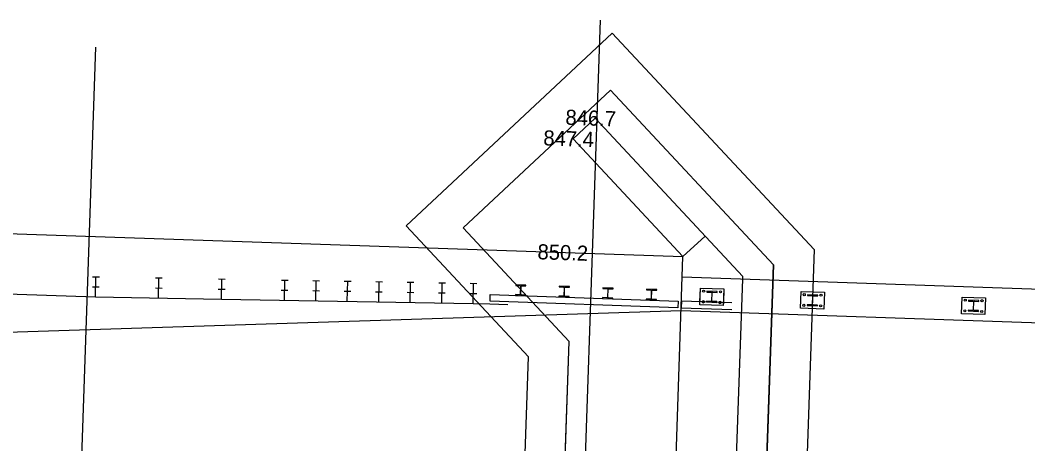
# Model space of a CAD drawing. Extents: x 2191309 to 2193046, y 863659 to 865133.
# Drawn here: x 2191665.3 to 2191715.3, y 865094.6 to 865115.6 of the extents above; entities that cross this region are included whole.
import ezdxf

# ---------------------------------------------------------------- set-up
doc = ezdxf.new("R2010")
doc.units = 0
for name, color, linetype in [('D_Bridge_Abutment', 7, 'Continuous'), ('D_Bridge_Deck', 7, 'Continuous'), ('D_Bridge_Railing', 7, 'Continuous'), ('D_Bridge_Substructure_Hidden', 7, 'Continuous'), ('D_Guardrail_Beam_Lt', 7, 'Continuous'), ('D_Roadway_Edge_Shoulder', 7, 'Continuous'), ('D_Roadway_Edge_TW', 7, 'Continuous'), ('H_V CONTROLS', 7, 'Continuous'), ('JUNK', 7, 'Continuous')]:
    doc.layers.add(name, color=color, linetype=linetype)

msp = doc.modelspace()

# ---------------------------------------------------------------- linework, layer by layer
at = {"layer": 'D_Bridge_Abutment'}
for p, q in [((2191692.707, 865109.691), (2191693.804, 865110.715)), ((2191701.135, 865102.863), (2191693.804, 865110.715)), ((2191698.167, 865103.844), (2191692.707, 865109.691)), ((2191698.167, 865103.844), (2191699.263, 865104.867)), ((2191697, 865069.864), (2191698.167, 865103.844)), ((2191701.131, 865102.741), (2191701.135, 865102.863))]:
    msp.add_line(p, q, dxfattribs=at)
at = {"layer": 'D_Bridge_Deck'}
for p, q in [((2191698.132, 865102.844), (2191735.111, 865101.575)), ((2191698.075, 865101.179), (2191735.053, 865099.909))]:
    msp.add_line(p, q, dxfattribs=at)
at = {"layer": 'D_Bridge_Railing'}
for p, q in [((2191689.861, 865102.451), (2191689.859, 865102.413)), ((2191689.859, 865102.413), (2191690.069, 865102.406)), ((2191690.367, 865102.434), (2191689.861, 865102.451)), ((2191690.098, 865102.375), (2191690.085, 865101.979)), ((2191690.111, 865101.978), (2191690.125, 865102.374)), ((2191690.156, 865102.403), (2191690.366, 865102.396)), ((2191690.366, 865102.396), (2191690.367, 865102.434)), ((2191692.026, 865102.377), (2191692.025, 865102.339)), ((2191692.025, 865102.339), (2191692.235, 865102.332)), ((2191692.532, 865102.359), (2191692.026, 865102.377)), ((2191692.264, 865102.301), (2191692.25, 865101.905)), ((2191692.277, 865101.904), (2191692.29, 865102.3)), ((2191692.321, 865102.329), (2191692.531, 865102.321)), ((2191692.531, 865102.321), (2191692.532, 865102.359)), ((2191694.191, 865102.302), (2191694.19, 865102.264)), ((2191694.19, 865102.264), (2191694.4, 865102.257)), ((2191694.698, 865102.285), (2191694.191, 865102.302)), ((2191694.429, 865102.226), (2191694.415, 865101.83)), ((2191694.442, 865101.829), (2191694.456, 865102.226)), ((2191694.486, 865102.254), (2191694.696, 865102.247)), ((2191694.696, 865102.247), (2191694.698, 865102.285)), ((2191696.357, 865102.228), (2191696.355, 865102.19)), ((2191696.355, 865102.19), (2191696.566, 865102.183)), ((2191696.863, 865102.211), (2191696.357, 865102.228)), ((2191696.652, 865102.18), (2191696.862, 865102.173)), ((2191696.862, 865102.173), (2191696.863, 865102.211)), ((2191689.844, 865101.958), (2191689.842, 865101.92)), ((2191689.842, 865101.92), (2191690.349, 865101.902)), ((2191690.054, 865101.95), (2191689.844, 865101.958)), ((2191690.35, 865101.94), (2191690.14, 865101.947)), ((2191690.349, 865101.902), (2191690.35, 865101.94)), ((2191692.009, 865101.883), (2191692.008, 865101.845)), ((2191692.008, 865101.845), (2191692.514, 865101.828)), ((2191692.219, 865101.876), (2191692.009, 865101.883)), ((2191692.515, 865101.866), (2191692.305, 865101.873)), ((2191692.514, 865101.828), (2191692.515, 865101.866)), ((2191694.174, 865101.809), (2191694.173, 865101.771)), ((2191694.173, 865101.771), (2191694.68, 865101.754)), ((2191694.385, 865101.802), (2191694.174, 865101.809)), ((2191694.681, 865101.791), (2191694.471, 865101.799)), ((2191694.68, 865101.754), (2191694.681, 865101.791)), ((2191696.34, 865101.735), (2191696.339, 865101.697)), ((2191696.339, 865101.697), (2191696.845, 865101.679)), ((2191696.55, 865101.727), (2191696.34, 865101.735)), ((2191696.594, 865102.152), (2191696.581, 865101.756)), ((2191696.607, 865101.755), (2191696.621, 865102.151)), ((2191696.846, 865101.717), (2191696.636, 865101.724)), ((2191696.845, 865101.679), (2191696.846, 865101.717)), ((2191699.353, 865102.125), (2191699.352, 865102.088)), ((2191699.352, 865102.088), (2191699.563, 865102.081)), ((2191699.863, 865102.107), (2191699.353, 865102.125)), ((2191699.355, 865102.125), (2191699.354, 865102.087)), ((2191699.354, 865102.087), (2191699.564, 865102.08)), ((2191699.861, 865102.108), (2191699.355, 865102.125)), ((2191699.593, 865102.049), (2191699.579, 865101.653)), ((2191699.593, 865102.049), (2191699.579, 865101.653)), ((2191699.605, 865101.652), (2191699.619, 865102.048)), ((2191699.606, 865101.652), (2191699.619, 865102.048)), ((2191699.65, 865102.077), (2191699.86, 865102.07)), ((2191699.651, 865102.078), (2191699.862, 865102.071)), ((2191699.86, 865102.07), (2191699.861, 865102.108)), ((2191699.862, 865102.071), (2191699.863, 865102.107)), ((2191704.35, 865101.953), (2191704.349, 865101.917)), ((2191704.349, 865101.917), (2191704.56, 865101.91)), ((2191704.86, 865101.936), (2191704.35, 865101.953)), ((2191704.59, 865101.878), (2191704.576, 865101.481)), ((2191704.602, 865101.48), (2191704.616, 865101.877)), ((2191704.648, 865101.907), (2191704.859, 865101.899)), ((2191704.859, 865101.899), (2191704.86, 865101.936)), ((2191712.345, 865101.679), (2191712.344, 865101.642)), ((2191712.856, 865101.661), (2191712.345, 865101.679)), ((2191699.336, 865101.63), (2191699.335, 865101.594)), ((2191699.335, 865101.594), (2191699.845, 865101.576)), ((2191699.547, 865101.623), (2191699.336, 865101.63)), ((2191699.338, 865101.632), (2191699.337, 865101.594)), ((2191699.337, 865101.594), (2191699.843, 865101.576)), ((2191699.548, 865101.624), (2191699.338, 865101.632)), ((2191699.844, 865101.614), (2191699.634, 865101.621)), ((2191699.846, 865101.613), (2191699.635, 865101.62)), ((2191699.843, 865101.576), (2191699.844, 865101.614)), ((2191699.845, 865101.576), (2191699.846, 865101.613)), ((2191704.333, 865101.459), (2191704.332, 865101.422)), ((2191704.332, 865101.422), (2191704.842, 865101.405)), ((2191704.544, 865101.451), (2191704.333, 865101.459)), ((2191704.843, 865101.441), (2191704.632, 865101.448)), ((2191704.842, 865101.405), (2191704.843, 865101.441)), ((2191712.329, 865101.184), (2191712.327, 865101.148)), ((2191712.54, 865101.177), (2191712.329, 865101.184)), ((2191712.344, 865101.642), (2191712.555, 865101.635)), ((2191712.585, 865101.603), (2191712.572, 865101.207)), ((2191712.598, 865101.206), (2191712.611, 865101.602)), ((2191712.839, 865101.167), (2191712.627, 865101.174)), ((2191712.643, 865101.632), (2191712.854, 865101.625)), ((2191712.837, 865101.13), (2191712.839, 865101.167)), ((2191712.854, 865101.625), (2191712.856, 865101.661)), ((2191712.327, 865101.148), (2191712.837, 865101.13))]:
    msp.add_line(p, q, dxfattribs=at)
for points in [[(2191699.03, 865102.287), (2191700.196, 865102.247), (2191700.168, 865101.414), (2191699.002, 865101.454)], [(2191704.027, 865102.115), (2191705.193, 865102.075), (2191705.165, 865101.243), (2191703.999, 865101.283)], [(2191712.023, 865101.841), (2191713.189, 865101.801), (2191713.16, 865100.968), (2191711.994, 865101.008)]]:
    msp.add_lwpolyline(points, close=True, dxfattribs=at)
for points in [[(2191699.007, 865101.605), (2191699.03, 865102.287), (2191700.196, 865102.247), (2191700.173, 865101.565)], [(2191688.596, 865101.962), (2191697.924, 865101.642), (2191697.913, 865101.309), (2191688.585, 865101.629), (2191688.596, 865101.962)], [(2191700.595, 865101.551), (2191698.091, 865101.637), (2191698.079, 865101.303), (2191700.584, 865101.217)], [(2191700.173, 865101.565), (2191700.168, 865101.414), (2191699.002, 865101.454), (2191699.007, 865101.605)]]:
    msp.add_lwpolyline(points, dxfattribs=at)
for centre in [(2191699.192, 865102.13), (2191699.192, 865102.13), (2191700.025, 865102.102), (2191700.025, 865102.102), (2191704.189, 865101.959), (2191705.022, 865101.93), (2191712.184, 865101.684), (2191713.017, 865101.656), (2191699.174, 865101.599), (2191700.006, 865101.571), (2191704.171, 865101.428), (2191705.003, 865101.399), (2191712.166, 865101.153), (2191712.999, 865101.125)]:
    msp.add_circle(centre, 0.0521, dxfattribs=at)
for centre, radius, start, end in [((2191690.068, 865102.376), 0.0298, 358.0343, 88.0343), ((2191690.155, 865102.373), 0.0298, 88.0343, 178.0343), ((2191692.234, 865102.302), 0.0298, 358.0343, 88.0343), ((2191692.32, 865102.299), 0.0298, 88.0343, 178.0343), ((2191694.399, 865102.227), 0.0298, 358.0343, 88.0343), ((2191694.485, 865102.224), 0.0298, 88.0343, 178.0343), ((2191696.565, 865102.153), 0.0298, 358.0343, 88.0343), ((2191696.651, 865102.15), 0.0298, 88.0343, 178.0343), ((2191690.055, 865101.98), 0.0298, 268.0343, 358.0343), ((2191690.141, 865101.977), 0.0298, 178.0343, 268.0343), ((2191692.22, 865101.906), 0.0298, 268.0343, 358.0343), ((2191692.306, 865101.903), 0.0298, 178.0343, 268.0343), ((2191694.386, 865101.831), 0.0298, 268.0343, 358.0343), ((2191694.472, 865101.828), 0.0298, 178.0343, 268.0343), ((2191696.551, 865101.757), 0.0298, 268.0343, 358.0343), ((2191696.637, 865101.754), 0.0298, 178.0343, 268.0343), ((2191699.562, 865102.05), 0.0308, 358.0343, 88.0343), ((2191699.563, 865102.05), 0.0298, 358.0343, 88.0343), ((2191699.65, 865102.047), 0.0308, 88.0343, 178.0343), ((2191699.649, 865102.047), 0.0298, 88.0343, 178.0343), ((2191704.559, 865101.879), 0.0308, 358.0343, 88.0343), ((2191704.647, 865101.876), 0.0308, 88.0343, 178.0343), ((2191699.548, 865101.654), 0.0308, 268.0343, 358.0343), ((2191699.549, 865101.654), 0.0298, 268.0343, 358.0343), ((2191699.636, 865101.651), 0.0308, 178.0343, 268.0343), ((2191699.635, 865101.651), 0.0298, 178.0343, 268.0343), ((2191704.546, 865101.482), 0.0308, 268.0343, 358.0343), ((2191704.633, 865101.479), 0.0308, 178.0343, 268.0343), ((2191712.541, 865101.208), 0.0308, 268.0343, 358.0343), ((2191712.554, 865101.604), 0.0308, 358.0343, 88.0343), ((2191712.628, 865101.205), 0.0308, 178.0343, 268.0343), ((2191712.642, 865101.601), 0.0308, 88.0343, 178.0343)]:
    msp.add_arc(centre, radius, start, end, dxfattribs=at)
at = {"layer": 'D_Bridge_Substructure_Hidden'}
for p, q in [((2191687.249, 865105.28), (2191694.559, 865112.104)), ((2191702.655, 865103.432), (2191694.559, 865112.104)), ((2191692.519, 865099.636), (2191687.249, 865105.28)), ((2191701.507, 865069.967), (2191702.655, 865103.432)), ((2191700.044, 865071.093), (2191701.131, 865102.741)), ((2191691.654, 865074.449), (2191692.519, 865099.636))]:
    msp.add_line(p, q, dxfattribs=at)
at = {"layer": 'D_Guardrail_Beam_Lt'}
for p, q in [((2191668.851, 865102.846), (2191669.184, 865102.84)), ((2191669, 865101.843), (2191669.018, 865102.843)), ((2191671.976, 865102.792), (2191672.309, 865102.786)), ((2191672.125, 865101.789), (2191672.142, 865102.789)), ((2191675.1, 865102.738), (2191675.433, 865102.732)), ((2191675.249, 865101.735), (2191675.267, 865102.735)), ((2191678.225, 865102.684), (2191678.558, 865102.678)), ((2191678.374, 865101.681), (2191678.391, 865102.681)), ((2191668.842, 865102.346), (2191669.176, 865102.34)), ((2191671.967, 865102.292), (2191672.3, 865102.286)), ((2191675.091, 865102.238), (2191675.425, 865102.232)), ((2191678.216, 865102.184), (2191678.549, 865102.178)), ((2191679.787, 865102.657), (2191680.12, 865102.651)), ((2191679.936, 865101.654), (2191679.953, 865102.654)), ((2191681.349, 865102.63), (2191681.682, 865102.624)), ((2191681.498, 865101.627), (2191681.516, 865102.627)), ((2191682.911, 865102.603), (2191683.245, 865102.597)), ((2191683.061, 865101.6), (2191683.078, 865102.6)), ((2191684.474, 865102.576), (2191684.807, 865102.57)), ((2191684.623, 865101.573), (2191684.64, 865102.573)), ((2191686.036, 865102.549), (2191686.369, 865102.543)), ((2191686.185, 865101.546), (2191686.203, 865102.546)), ((2191687.598, 865102.522), (2191687.931, 865102.516)), ((2191687.748, 865101.519), (2191687.765, 865102.519)), ((2191659.631, 865102.165), (2191669, 865101.843)), ((2191669, 865101.843), (2191675.249, 865101.735)), ((2191675.249, 865101.735), (2191687.748, 865101.519)), ((2191679.778, 865102.157), (2191680.111, 865102.151)), ((2191681.34, 865102.13), (2191681.674, 865102.124)), ((2191682.903, 865102.103), (2191683.236, 865102.097)), ((2191684.465, 865102.076), (2191684.798, 865102.07)), ((2191686.027, 865102.049), (2191686.361, 865102.043)), ((2191687.59, 865102.022), (2191687.923, 865102.016)), ((2191687.748, 865101.519), (2191688.581, 865101.505)), ((2191688.581, 865101.505), (2191689.476, 865101.474))]:
    msp.add_line(p, q, dxfattribs=at)
for centre, start, end in [((2191699.174, 865101.599), 178.0343, 358.0343), ((2191699.174, 865101.599), 358.0343, 178.0343), ((2191700.006, 865101.571), 358.0343, 178.0343), ((2191700.006, 865101.571), 178.0343, 358.0343)]:
    msp.add_arc(centre, 0.0521, start, end, dxfattribs=at)
at = {"layer": 'D_Roadway_Edge_Shoulder'}
msp.add_line((2191659.734, 865105.163), (2191698.167, 865103.844), dxfattribs=at)
at = {"layer": 'D_Roadway_Edge_TW'}
msp.add_lwpolyline([(2191518.589, 865104.656), (2191543.552, 865103.147), (2191648.101, 865099.559), (2191698.075, 865101.179)], dxfattribs=at)
at = {"layer": 'H_V CONTROLS'}
msp.add_lwpolyline([(2191687.249, 865105.28), (2191694.559, 865112.104), (2191702.655, 865103.432), (2191701.507, 865069.967), (2191692.835, 865061.87), (2191686.01, 865069.18), (2191691.654, 865074.449), (2191692.519, 865099.636), (2191687.249, 865105.28)], dxfattribs=at)
at = {"layer": 'JUNK'}
for p, q in [((2191693.086, 865087.008), (2191694.067, 865115.576)), ((2191668.101, 865087.866), (2191669.006, 865114.236))]:
    msp.add_line(p, q, dxfattribs=at)
msp.add_lwpolyline([(2191684.423, 865105.377), (2191694.656, 865114.931), (2191704.682, 865104.192), (2191703.477, 865069.07), (2191692.738, 865059.043), (2191683.184, 865069.277), (2191689.684, 865075.346), (2191690.492, 865098.876), (2191684.423, 865105.377)], dxfattribs=at)

# ---------------------------------------------------------------- texts
for s, p in [('846.7', (2191692.32, 865110.391)), ('847.4', (2191691.223, 865109.367)), ('850.2', (2191690.932, 865103.717))]:
    msp.add_text(s, height=0.75, rotation=358.0343, dxfattribs=at).set_placement(p)

doc.saveas('drawing.dxf')
